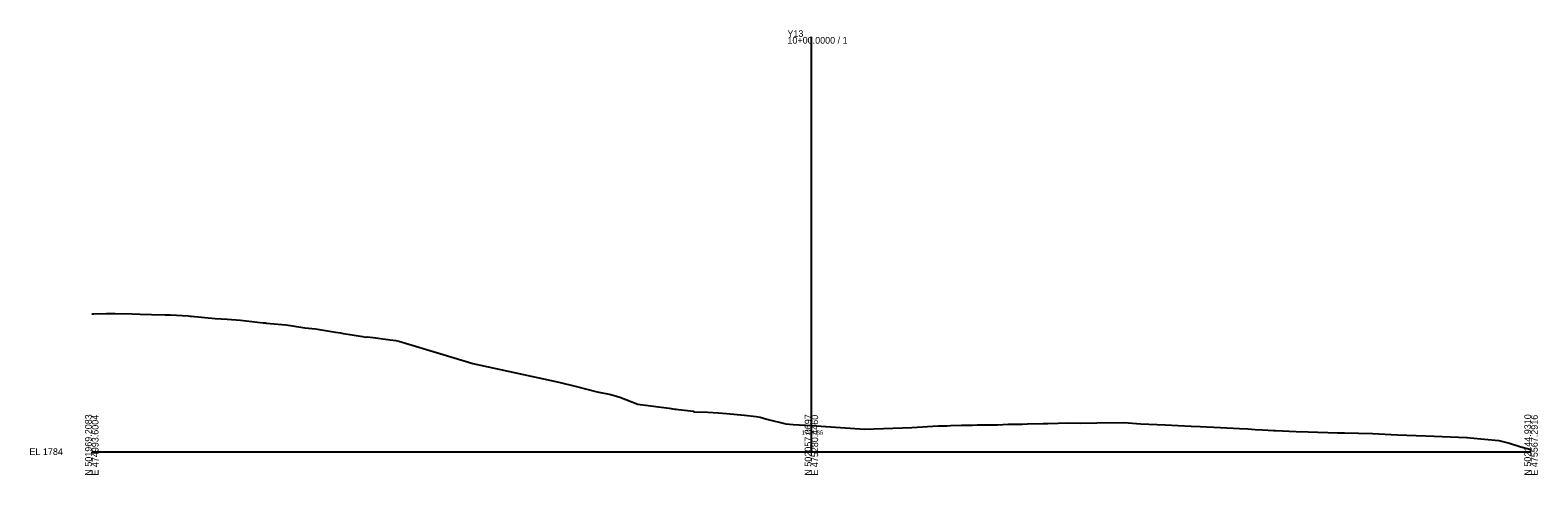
# Model space of a CAD drawing. Extents: x -126 to 503, y -10 to 2750.
# Drawn here: x -126 to 503, y -10 to 176 of the extents above; entities that cross this region are included whole.
import ezdxf

# ---------------------------------------------------------------- set-up
doc = ezdxf.new("R2010")
doc.units = 0
for name, color, linetype in [('Exist Cross Section Cell', 7, 'Continuous'), ('Exist XS Center Line Elevation Label', 7, 'Continuous'), ('Exist XS Ground Line', 7, 'Continuous')]:
    doc.layers.add(name, color=color, linetype=linetype)

msp = doc.modelspace()

# ---------------------------------------------------------------- linework, layer by layer
at = {"layer": 'Exist Cross Section Cell'}
for p, q in [((200, 0), (200, 173.14)), ((-100, 0), (200, 0)), ((200, 0), (500, 0))]:
    msp.add_line(p, q, dxfattribs=at)
at = {"layer": 'Exist XS Ground Line'}
msp.add_lwpolyline([(-100, 57.6), (-99.1, 57.6), (-93.92, 57.7), (-91.11, 57.71), (-90.25, 57.71), (-83.12, 57.48), (-79.82, 57.41), (-75.12, 57.29), (-69.38, 57.17), (-67.13, 57.1), (-59.77, 56.65), (-58.94, 56.59), (-58.57, 56.56), (-48.5, 55.64), (-43.53, 55.25), (-38.05, 54.89), (-28.49, 53.82), (-27.62, 53.73), (-27.15, 53.67), (-25.63, 53.54), (-19.16, 52.98), (-17.18, 52.67), (-11.17, 51.75), (-6.74, 51.24), (1.59, 49.88), (3.7, 49.61), (4.82, 49.35), (8.48, 48.78), (12.81, 48.06), (14.13, 47.81), (14.77, 47.99), (17.35, 47.6), (24.36, 46.67), (26.82, 46.34), (28.04, 46.18), (46.42, 40.55), (58.8, 36.79), (94.75, 29.08), (101.54, 27.38), (110.64, 24.91), (116.4, 23.85), (120.17, 22.71), (127.66, 19.86), (128.56, 19.74), (140.7, 18.1), (143.03, 17.81), (143.68, 17.69), (144.63, 17.59), (150.87, 16.85), (151.04, 16.68), (156.81, 16.43), (161.11, 16.23), (164.56, 15.93), (172.08, 15.27), (177.01, 14.69), (178.68, 14.42), (181.35, 13.62), (189.35, 11.67), (192.46, 11.34), (200, 10.86), (222.11, 9.44), (241.9, 10.04), (252.9, 10.75), (256.66, 10.84), (258.03, 10.87), (262.51, 11), (266.04, 11.09), (267.12, 11.11), (269.15, 11.16), (277.58, 11.23), (282.05, 11.44), (288.04, 11.53), (290.06, 11.6), (296.66, 11.7), (298.52, 11.72), (307.24, 11.98), (312.22, 11.96), (318.97, 11.97), (330.19, 12.12), (337.28, 11.59), (347.51, 11.14), (358.33, 10.64), (362.07, 10.48), (370.58, 10.06), (378.47, 9.72), (381.87, 9.54), (384.93, 9.24), (388.09, 9.14), (392.67, 8.9), (393.5, 8.81), (402.15, 8.47), (407.06, 8.28), (419.31, 7.93), (420.28, 7.91), (422.24, 7.85), (433.88, 7.58), (444.3, 7.05), (452.12, 6.76), (456.08, 6.63), (473.18, 5.92), (473.53, 5.91), (474.63, 5.8), (486.62, 4.69), (491.09, 3.52), (495.72, 1.99), (498.96, 1.14), (500, 0.79)], dxfattribs=at)

# ---------------------------------------------------------------- texts
at = {"layer": 'Exist Cross Section Cell'}
for s, p in [('Y13', (190, 173.14)), ('10+00.0000 / 1', (190, 170.34)), ('EL 1784', (-126, -1.4))]:
    msp.add_text(s, height=2.8, dxfattribs=at).set_placement(p)
for s, p in [('N 501969.2083', (-100, -10)), ('E 474993.6004', (-97.2, -10)), ('N 502057.0697', (200, -10)), ('E 475280.4460', (202.8, -10)), ('N 502144.9310', (500, -10)), ('E 475567.2916', (502.8, -10))]:
    msp.add_text(s, height=2.8, rotation=90, dxfattribs=at).set_placement(p)
at = {"layer": 'Exist XS Center Line Elevation Label'}
msp.add_text('1794.86', height=1.8, dxfattribs=at).set_placement((195.92, 7.06))

doc.saveas('drawing.dxf')
